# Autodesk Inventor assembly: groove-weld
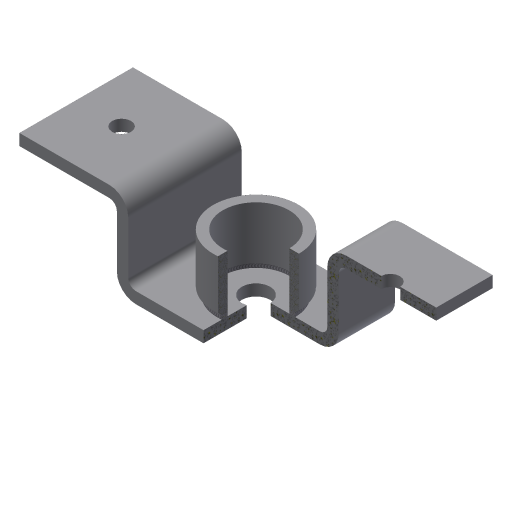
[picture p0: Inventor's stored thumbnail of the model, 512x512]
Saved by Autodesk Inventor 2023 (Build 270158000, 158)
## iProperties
Created: 2005-03
Part Number: groove-weld
Document SubType Name: Weldment
Designer: CADCIM
Manufacturer: Standard
Standards Organization: Custom
Author: CADCIM
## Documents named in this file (3)
- D:\PROJECTS\Project 2022\Autodesk Inventor For Professional 2023\RESOURCES INVENTOR 2023\RESOURCES INVENTOR 2023\Inventor_2023_Part\Inventor_2023_Part\c16_Inv_2023_prt\fig 16-16\groove-weld.iam
- D:\PROJECTS\Project 2022\Autodesk Inventor For Professional 2023\RESOURCES INVENTOR 2023\RESOURCES INVENTOR 2023\Inventor_2023_Part\Inventor_2023_Part\c16_Inv_2023_prt\fig 16-16\Bracket.ipt
- D:\PROJECTS\Project 2022\Autodesk Inventor For Professional 2023\RESOURCES INVENTOR 2023\RESOURCES INVENTOR 2023\Inventor_2023_Part\Inventor_2023_Part\c16_Inv_2023_prt\fig 16-16\cylinder.ipt
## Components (2 placed, 2 different names)
1. Bracket:1 — Insert:1
2. cylinder:1 — Insert:1
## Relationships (1: Insert 1)
- Insert:1: Bracket:1 ↔ cylinder:1
